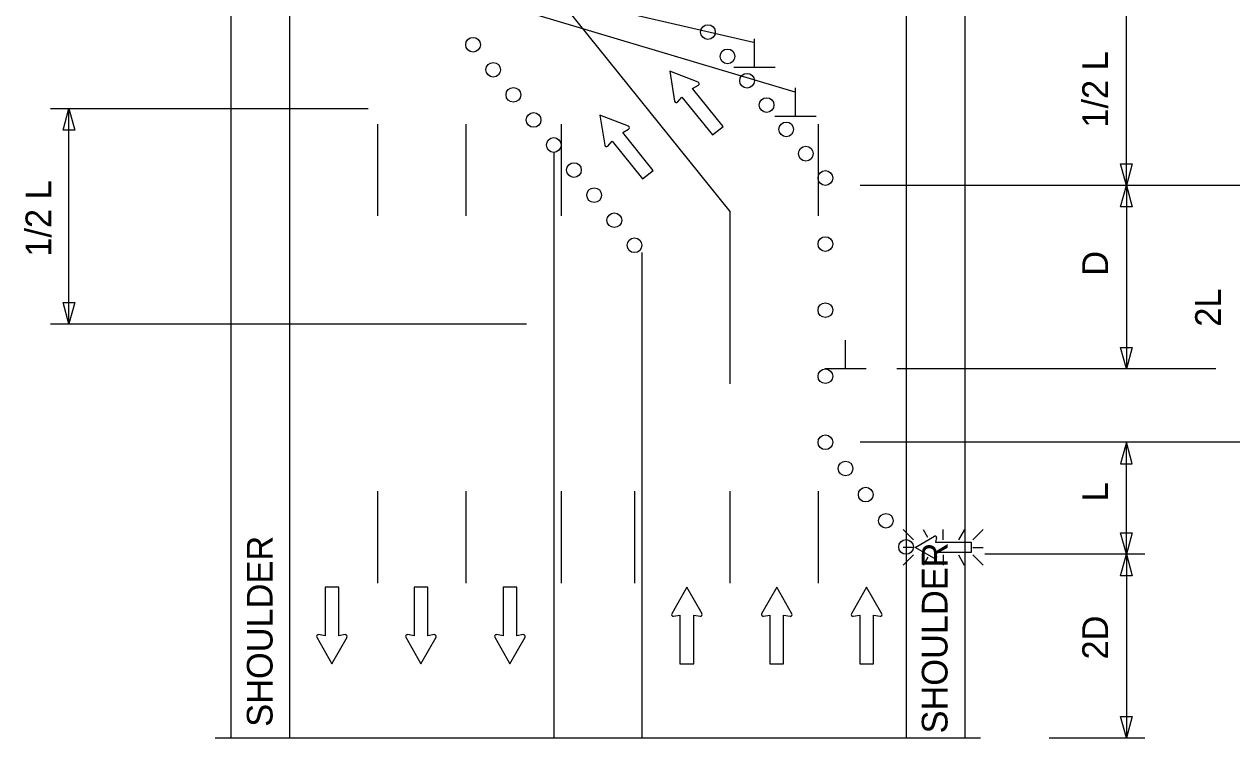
# Model space of a CAD drawing. Extents: x 16544 to 19504, y 5662 to 6922.
# Drawn here: x 16867.2 to 17196.2, y 6074.1 to 6268.5 of the extents above; entities that cross this region are included whole.
import ezdxf

# ---------------------------------------------------------------- set-up
doc = ezdxf.new("R2010")
doc.units = 0
for name, color, linetype in [('ALI_LEGAL_EX', 7, 'Continuous'), ('MT_SCRATCH_LEVEL_E', 7, 'Continuous'), ('PAVT_EDGE_EX', 7, 'Continuous'), ('TRAFFIC_SIGNS_PR', 7, 'Continuous'), ('TYPICAL_TEXT_DIMEN_PR', 7, 'Continuous')]:
    doc.layers.add(name, color=color, linetype=linetype)

msp = doc.modelspace()

# ---------------------------------------------------------------- linework, layer by layer
at = {"layer": 'ALI_LEGAL_EX'}
for points in [[(16963.46, 6241.23), (16963.46, 6216.23)], [(16987.46, 6241.23), (16987.46, 6216.23)], [(17013.46, 6241.23), (17013.46, 6216.23)], [(17083.46, 6241.23), (17083.46, 6216.23)], [(16963.46, 6141.23), (16963.46, 6116.23)], [(16987.46, 6141.23), (16987.46, 6116.23)], [(17013.46, 6141.23), (17013.46, 6116.23)], [(17033.46, 6141.23), (17033.46, 6116.23)], [(17059.46, 6141.23), (17059.46, 6116.23)], [(17083.46, 6141.23), (17083.46, 6116.23)]]:
    msp.add_lwpolyline(points, dxfattribs=at)
at = {"layer": 'MT_SCRATCH_LEVEL_E'}
for p, q in [((17043.04, 6255.7), (17044.38, 6247.48)), ((17050.81, 6252.66), (17043.04, 6255.7)), ((17043.04, 6255.7), (17044.38, 6247.48)), ((17050.81, 6252.66), (17043.04, 6255.7)), ((17045.18, 6247.25), (17046.37, 6248.61)), ((17045.18, 6247.25), (17046.37, 6248.61)), ((17046.37, 6248.61), (17054.68, 6238.28)), ((17046.37, 6248.61), (17054.68, 6238.28)), ((17049.28, 6250.95), (17050.86, 6251.82)), ((17049.28, 6250.95), (17050.86, 6251.82)), ((17057.6, 6240.63), (17049.28, 6250.95)), ((17057.6, 6240.63), (17049.28, 6250.95)), ((17024.01, 6243.71), (17025.35, 6235.49)), ((17031.78, 6240.67), (17024.01, 6243.71)), ((17024.01, 6243.71), (17025.35, 6235.49)), ((17031.78, 6240.67), (17024.01, 6243.71)), ((17030.26, 6238.96), (17031.84, 6239.83)), ((17030.26, 6238.96), (17031.84, 6239.83)), ((17038.57, 6228.64), (17030.26, 6238.96)), ((17038.57, 6228.64), (17030.26, 6238.96)), ((17054.68, 6238.28), (17057.6, 6240.63)), ((17054.68, 6238.28), (17057.6, 6240.63)), ((17026.15, 6235.26), (17027.34, 6236.62)), ((17026.15, 6235.26), (17027.34, 6236.62)), ((17027.34, 6236.62), (17035.66, 6226.29)), ((17027.34, 6236.62), (17035.66, 6226.29)), ((17035.66, 6226.29), (17038.57, 6228.64)), ((17035.66, 6226.29), (17038.57, 6228.64)), ((16952.87, 6115.1), (16949.13, 6115.1)), ((16949.13, 6115.1), (16949.13, 6101.84)), ((16952.87, 6115.1), (16949.13, 6115.1)), ((16949.13, 6115.1), (16949.13, 6101.84)), ((16952.87, 6101.84), (16952.87, 6115.1)), ((16952.87, 6101.84), (16952.87, 6115.1)), ((16977.13, 6115.1), (16973.39, 6115.1)), ((16973.39, 6115.1), (16973.39, 6101.84)), ((16977.13, 6115.1), (16973.39, 6115.1)), ((16973.39, 6115.1), (16973.39, 6101.84)), ((16977.13, 6101.84), (16977.13, 6115.1)), ((16977.13, 6101.84), (16977.13, 6115.1)), ((17001.39, 6115.1), (16997.64, 6115.1)), ((16997.64, 6115.1), (16997.64, 6101.84)), ((17001.39, 6115.1), (16997.64, 6115.1)), ((16997.64, 6115.1), (16997.64, 6101.84)), ((17001.39, 6101.84), (17001.39, 6115.1)), ((17001.39, 6101.84), (17001.39, 6115.1)), ((17047.7, 6115.1), (17043.59, 6107.86)), ((17047.7, 6115.1), (17043.59, 6107.86)), ((17051.85, 6107.86), (17047.7, 6115.1)), ((17051.85, 6107.86), (17047.7, 6115.1)), ((17072.2, 6115.1), (17068.09, 6107.86)), ((17072.2, 6115.1), (17068.09, 6107.86)), ((17076.35, 6107.86), (17072.2, 6115.1)), ((17076.35, 6107.86), (17072.2, 6115.1)), ((17096.7, 6115.1), (17092.59, 6107.86)), ((17096.7, 6115.1), (17092.59, 6107.86)), ((17100.84, 6107.86), (17096.7, 6115.1)), ((17100.84, 6107.86), (17096.7, 6115.1)), ((17044.07, 6107.18), (17045.85, 6107.49)), ((17044.07, 6107.18), (17045.85, 6107.49)), ((17045.85, 6107.49), (17045.85, 6094.23)), ((17045.85, 6107.49), (17045.85, 6094.23)), ((17049.59, 6094.23), (17049.59, 6107.49)), ((17049.59, 6107.49), (17051.37, 6107.18)), ((17049.59, 6094.23), (17049.59, 6107.49)), ((17049.59, 6107.49), (17051.37, 6107.18)), ((17068.57, 6107.18), (17070.35, 6107.49)), ((17068.57, 6107.18), (17070.35, 6107.49)), ((17070.35, 6107.49), (17070.35, 6094.23)), ((17070.35, 6107.49), (17070.35, 6094.23)), ((17074.09, 6094.23), (17074.09, 6107.49)), ((17074.09, 6107.49), (17075.87, 6107.18)), ((17074.09, 6094.23), (17074.09, 6107.49)), ((17074.09, 6107.49), (17075.87, 6107.18)), ((17093.07, 6107.18), (17094.85, 6107.49)), ((17093.07, 6107.18), (17094.85, 6107.49)), ((17094.85, 6107.49), (17094.85, 6094.23)), ((17094.85, 6107.49), (17094.85, 6094.23)), ((17098.59, 6094.23), (17098.59, 6107.49)), ((17098.59, 6107.49), (17100.36, 6107.18)), ((17098.59, 6094.23), (17098.59, 6107.49)), ((17098.59, 6107.49), (17100.36, 6107.18)), ((16946.87, 6101.47), (16951.02, 6094.23)), ((16946.87, 6101.47), (16951.02, 6094.23)), ((16949.13, 6101.84), (16947.35, 6102.16)), ((16949.13, 6101.84), (16947.35, 6102.16)), ((16951.02, 6094.23), (16955.13, 6101.47)), ((16951.02, 6094.23), (16955.13, 6101.47)), ((16954.65, 6102.16), (16952.87, 6101.84)), ((16954.65, 6102.16), (16952.87, 6101.84)), ((16971.13, 6101.47), (16975.28, 6094.23)), ((16971.13, 6101.47), (16975.28, 6094.23)), ((16973.39, 6101.84), (16971.61, 6102.16)), ((16973.39, 6101.84), (16971.61, 6102.16)), ((16975.28, 6094.23), (16979.39, 6101.47)), ((16975.28, 6094.23), (16979.39, 6101.47)), ((16978.91, 6102.16), (16977.13, 6101.84)), ((16978.91, 6102.16), (16977.13, 6101.84)), ((16995.39, 6101.47), (16999.53, 6094.23)), ((16995.39, 6101.47), (16999.53, 6094.23)), ((16997.64, 6101.84), (16995.87, 6102.16)), ((16997.64, 6101.84), (16995.87, 6102.16)), ((16999.53, 6094.23), (17003.64, 6101.47)), ((16999.53, 6094.23), (17003.64, 6101.47)), ((17003.16, 6102.16), (17001.39, 6101.84)), ((17003.16, 6102.16), (17001.39, 6101.84)), ((17045.85, 6094.23), (17049.59, 6094.23)), ((17045.85, 6094.23), (17049.59, 6094.23)), ((17070.35, 6094.23), (17074.09, 6094.23)), ((17070.35, 6094.23), (17074.09, 6094.23)), ((17094.85, 6094.23), (17098.59, 6094.23)), ((17094.85, 6094.23), (17098.59, 6094.23))]:
    msp.add_line(p, q, dxfattribs=at)
for centre, start, end in [((17050.63, 6252.23), 298.877, 68.6139), ((17050.63, 6252.23), 298.877, 68.6139), ((17044.84, 6247.56), 189.2656, 318.8046), ((17044.84, 6247.56), 189.2656, 318.8046), ((17031.6, 6240.24), 298.877, 68.6139), ((17031.6, 6240.24), 298.877, 68.6139), ((17025.81, 6235.57), 189.2656, 318.8046), ((17025.81, 6235.57), 189.2656, 318.8046), ((17044, 6107.64), 150.4248, 279.9638), ((17044, 6107.64), 150.4248, 279.9638), ((17051.44, 6107.64), 260.0362, 29.7731), ((17051.44, 6107.64), 260.0362, 29.7731), ((17068.5, 6107.64), 150.4248, 279.9638), ((17068.5, 6107.64), 150.4248, 279.9638), ((17075.94, 6107.64), 260.0362, 29.7731), ((17075.94, 6107.64), 260.0362, 29.7731), ((17092.99, 6107.64), 150.4248, 279.9638), ((17092.99, 6107.64), 150.4248, 279.9638), ((17100.43, 6107.64), 260.0362, 29.7731), ((17100.43, 6107.64), 260.0362, 29.7731), ((16947.28, 6101.7), 80.0362, 209.7731), ((16947.28, 6101.7), 80.0362, 209.7731), ((16954.72, 6101.7), 330.4248, 99.9638), ((16954.72, 6101.7), 330.4248, 99.9638), ((16971.54, 6101.7), 80.0362, 209.7731), ((16971.54, 6101.7), 80.0362, 209.7731), ((16978.98, 6101.7), 330.4248, 99.9638), ((16978.98, 6101.7), 330.4248, 99.9638), ((16995.8, 6101.7), 80.0362, 209.7731), ((16995.8, 6101.7), 80.0362, 209.7731), ((17003.24, 6101.7), 330.4248, 99.9638), ((17003.24, 6101.7), 330.4248, 99.9638)]:
    msp.add_arc(centre, 0.463, start, end, dxfattribs=at)
at = {"layer": 'PAVT_EDGE_EX'}
for p, q in [((16923.46, 6880.02), (16923.46, 6074.05)), ((16939.46, 6880.02), (16939.46, 6074.05)), ((17107.46, 6880.02), (17107.46, 6074.05)), ((17123.46, 6880.02), (17123.46, 6074.05)), ((17011.46, 6277.01), (17059.46, 6217.4)), ((17011.46, 6233.55), (17011.46, 6074.05)), ((17059.46, 6217.4), (17059.46, 6170.51)), ((17035.46, 6206.23), (17035.46, 6074.05))]:
    msp.add_line(p, q, dxfattribs=at)
at = {"layer": 'TRAFFIC_SIGNS_PR'}
for p, q in [((17106.65, 6130.79), (17109.47, 6127.97)), ((17112.08, 6130.79), (17113.29, 6128.7)), ((17117.55, 6127.97), (17117.55, 6130.79)), ((17123.34, 6130.79), (17121.71, 6127.97)), ((17125.64, 6127.97), (17128.46, 6130.8)), ((17109.47, 6125.94), (17106.65, 6125.94)), ((17106.65, 6121.09), (17109.47, 6123.91)), ((17117.55, 6123.91), (17117.55, 6121.09)), ((17121.69, 6123.91), (17123.32, 6121.09)), ((17125.64, 6125.94), (17128.46, 6125.94)), ((17125.64, 6123.91), (17128.46, 6121.09)), ((17113.37, 6123.28), (17112.11, 6121.09))]:
    msp.add_line(p, q, dxfattribs=at)
for points in [[(17115.23, 6122.93), (17109.92, 6125.94), (17115.23, 6128.98)], [(17115.73, 6128.62), (17115.5, 6127.33), (17125.22, 6127.33), (17125.22, 6124.58), (17115.5, 6124.58), (17115.73, 6123.28)]]:
    msp.add_lwpolyline(points, dxfattribs=at)
for centre in [(17053.46, 6266.31), (16989.46, 6262.87), (16989.46, 6262.87), (16989.46, 6262.87), (17058.79, 6259.68), (16994.96, 6256.04), (17064.13, 6253.06), (17000.46, 6249.21), (17069.46, 6246.43), (17005.96, 6242.38), (17074.79, 6239.81), (17011.46, 6235.55), (17080.13, 6233.19), (17016.96, 6228.72), (17085.46, 6226.56), (17022.46, 6221.89), (17027.96, 6215.06), (17033.46, 6208.23), (17085.46, 6208.56), (17085.46, 6190.56), (17085.46, 6172.56), (17085.46, 6154.56), (17090.96, 6147.43), (17096.45, 6140.3), (17101.95, 6133.18), (17107.45, 6126.05)]:
    msp.add_circle(centre, 2, dxfattribs=at)
for centre, start, end in [((17115.39, 6128.68), 350.0407, 118.5167), ((17115.39, 6123.23), 241.1084, 9.2692)]:
    msp.add_arc(centre, 0.341, start, end, dxfattribs=at)
at = {"layer": 'TYPICAL_TEXT_DIMEN_PR'}
for p, q in [((16911.62, 6299.38), (17065.88, 6263.52)), ((17077.2, 6249.98), (16911.62, 6299.38)), ((17167.46, 6224.56), (17167.46, 6277.01)), ((17066.17, 6256.65), (17066.17, 6264.44)), ((17071.8, 6256.65), (17060.55, 6256.65)), ((17077.34, 6243.33), (17077.34, 6251.12)), ((16874.36, 6245.47), (16960.87, 6245.47)), ((16877.79, 6239.61), (16879.36, 6245.47)), ((16879.36, 6186.83), (16879.36, 6245.47)), ((16879.36, 6245.47), (16880.93, 6239.61)), ((17082.97, 6243.33), (17071.72, 6243.33)), ((16879.36, 6239.61), (16877.79, 6239.61)), ((16880.93, 6239.61), (16879.36, 6239.61)), ((17167.46, 6224.56), (17165.89, 6230.43)), ((17165.89, 6230.43), (17167.46, 6230.43)), ((17167.46, 6230.43), (17169.03, 6230.43)), ((17169.03, 6230.43), (17167.46, 6224.56)), ((17203.04, 6224.56), (17094.92, 6224.56)), ((17172.46, 6224.56), (17134.08, 6224.56)), ((17165.89, 6218.7), (17167.46, 6224.56)), ((17167.46, 6224.56), (17167.46, 6174.56)), ((17167.46, 6224.56), (17169.03, 6218.7)), ((17167.46, 6218.7), (17165.89, 6218.7)), ((17169.03, 6218.7), (17167.46, 6218.7)), ((16879.36, 6186.83), (16877.79, 6192.69)), ((16877.79, 6192.69), (16879.36, 6192.69)), ((16879.36, 6192.69), (16880.93, 6192.69)), ((16880.93, 6192.69), (16879.36, 6186.83)), ((16874.36, 6186.83), (17003.99, 6186.83)), ((17090.97, 6174.56), (17090.97, 6182.35)), ((17167.46, 6174.56), (17165.89, 6180.43)), ((17165.89, 6180.43), (17167.46, 6180.43)), ((17167.46, 6180.43), (17169.03, 6180.43)), ((17169.03, 6180.43), (17167.46, 6174.56)), ((17096.59, 6174.56), (17085.34, 6174.56)), ((17191.85, 6174.56), (17104.96, 6174.56)), ((17203.04, 6154.56), (17094.92, 6154.56)), ((17167.46, 6154.56), (17165.89, 6148.7)), ((17167.46, 6124.05), (17167.46, 6154.56)), ((17169.03, 6148.7), (17167.46, 6154.56)), ((17165.89, 6148.7), (17167.46, 6148.7)), ((17167.46, 6148.7), (17169.03, 6148.7)), ((17167.46, 6124.05), (17165.89, 6129.91)), ((17165.89, 6129.91), (17167.46, 6129.91)), ((17167.46, 6129.91), (17169.03, 6129.91)), ((17169.03, 6129.91), (17167.46, 6124.05)), ((17172.46, 6124.05), (17128.9, 6124.05)), ((17165.89, 6118.19), (17167.46, 6124.05)), ((17167.46, 6124.05), (17169.03, 6118.19)), ((17167.46, 6124.05), (17167.46, 6074.05)), ((17167.46, 6118.19), (17165.89, 6118.19)), ((17169.03, 6118.19), (17167.46, 6118.19)), ((17167.46, 6074.05), (17165.89, 6079.91)), ((17165.89, 6079.91), (17167.46, 6079.91)), ((17167.46, 6079.91), (17169.03, 6079.91)), ((17169.03, 6079.91), (17167.46, 6074.05)), ((16919.16, 6074.05), (17127.76, 6074.05)), ((17011.46, 6074.05), (17035.46, 6074.05)), ((17011.46, 6074.05), (17035.46, 6074.05)), ((17146.46, 6074.05), (17172.46, 6074.05))]:
    msp.add_line(p, q, dxfattribs=at)

# ---------------------------------------------------------------- texts
for s, p in [('1/2 L', (17162.46, 6240.28)), ('1/2 L', (16874.53, 6205.12)), ('D', (17162.46, 6199.93)), ('2L', (17193.21, 6186.05)), ('L', (17162.46, 6138.45)), ('SHOULDER', (16934.84, 6077.07)), ('SHOULDER', (17118.74, 6075.25)), ('2D', (17162.46, 6095.39))]:
    msp.add_text(s, height=7, rotation=90, dxfattribs=at).set_placement(p)

doc.saveas('drawing.dxf')
